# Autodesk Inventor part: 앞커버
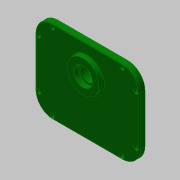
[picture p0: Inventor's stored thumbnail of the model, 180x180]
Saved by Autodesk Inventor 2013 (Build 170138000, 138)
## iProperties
Created: 2016-12
Part Number: 앞커버
Material: 일반
Document SubType Name: Modeling
Designer: mduedu
Density: 1 g/cm^3
Author: mduedu
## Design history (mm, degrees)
sketch "스케치1"
  geometry: L1 (-90, 42)-(-90, -42); L2 (-60, 72)-(60, 72); L3 (90, 42)-(90, -42); L4 (60, -72)-(-60, -72); A1 r 30 centre (-60, -42) between (-90, -42) and (-60, -72); A2 r 30 centre (60, 42) between (90, 42) and (60, 72); A3 r 30 centre (60, -42) between (60, -72) and (90, -42); A4 r 30 centre (-60, 42) between (-60, 72) and (-90, 42); 1 further point
  constraints: 8 end point, 8 point on circle, 8 tangent, 4 centre point, 3 equal radius, 2 perpendicular, 1 horizontal
  dimensions: "d89" = 30 radius of A2; "d116" = 180 distance between parallel lines of L3 L1; "d117" = 90 distance from line of point (0, 0) L1; "d118" = 72 distance from line of L2 point (0, 0); "d119" = 144 distance between parallel lines of L4 L2
extrude "돌출1" new body sketch "스케치1" distance "d3" = 10; taper "d4" = 0 deg
sketch "스케치2"
  geometry: C1 r 21 at (0, 26); 1 further point
  constraints: 1 centre point, 1 vertical alignment
  dimensions: "d5" = 42 diameter of C1; "d7" = 26 distance of C1.centre point (0, 0)
extrude "돌출2" join sketch "스케치2" distance "d8" = 7; taper "d9" = 0 deg
sketch "스케치3"
  geometry: C1 r 15 at (0, -28.87); C2 r 21 at (0, 26) reference; C3 r 15 at (-45.552, -28.87); C4 r 15 at (45.552, -28.87); 1 further point
  constraints: 3 centre point, 2 horizontal alignment, 1 vertical alignment
  dimensions: "d10" = 30 diameter of C1; "d71" = 54.87 distance of C1.centre C2.centre; "d120" = 30 diameter of C3; "d121" = 30 diameter of C4; "d122" = 45.552 distance of C3.centre C1.centre; "d123" = 45.552 distance of C4.centre C1.centre
extrude "돌출3" join sketch "스케치3" distance "d12" = 7; taper "d13" = 0 deg
sketch "스케치4"
  geometry: C1 r 21 at (0, 26) reference; C2 r 28 at (0, 26); 1 further point
  constraints: 1 centre point, 1 coincident
  dimensions: "d14" = 56 diameter of C2
extrude "돌출4" join sketch "스케치4" distance "d15" = 7; taper "d16" = -5 deg
hole "구멍1" diameter "d19" = 35; stored, may be unused: countersink angle "d23" = 90 deg, drill point angle "d25" = 0 deg; dims "d17" = 10, "d18" = 10, "d20" = 6, "d21" = 4, "d22" = 2, "d24" = 10
hole "구멍2" diameter "d28" = 22; stored, may be unused: countersink angle "d32" = 90 deg, drill point angle "d34" = 0 deg; dims "d26" = 10, "d27" = 10, "d29" = 6, "d30" = 4, "d31" = 2, "d33" = 7
hole "구멍8" diameter "d98" = 22; stored, may be unused: countersink angle "d102" = 90 deg, drill point angle "d104" = 0 deg; dims "d99" = 6, "d100" = 4, "d101" = 2, "d103" = 7, "d137" = 10, "d138" = 10
hole "구멍10" diameter "d128" = 22; stored, may be unused: countersink angle "d132" = 90 deg, drill point angle "d134" = 0 deg; dims "d129" = 6, "d130" = 4, "d131" = 2, "d133" = 7, "d135" = 10, "d136" = 10
hole "구멍3" diameter "d37" = 19; stored, may be unused: countersink angle "d41" = 90 deg, drill point angle "d43" = 0 deg; dims "d38" = 6, "d39" = 4, "d40" = 2, "d42" = 1, "d139" = 10, "d140" = 10
hole "구멍9" diameter "d107" = 19; stored, may be unused: countersink angle "d111" = 90 deg, drill point angle "d113" = 0 deg; dims "d108" = 6, "d109" = 4, "d110" = 2, "d112" = 1, "d141" = 10, "d142" = 10
hole "구멍11" diameter "d145" = 19; stored, may be unused: countersink angle "d149" = 90 deg, drill point angle "d151" = 0 deg; dims "d143" = 10, "d144" = 10, "d146" = 6, "d147" = 4, "d148" = 2, "d150" = 1
hole "구멍4" diameter "d46" = 32; stored, may be unused: countersink angle "d50" = 90 deg, drill point angle "d52" = 0 deg; dims "d47" = 6, "d48" = 4, "d49" = 2, "d51" = 8.3, "d154" = 10, "d155" = 10
hole "구멍5" diameter "d55" = 25; stored, may be unused: countersink angle "d59" = 90 deg, drill point angle "d61" = 0 deg; dims "d53" = 10, "d54" = 10, "d56" = 6, "d57" = 4, "d58" = 2, "d60" = 8
fillet "모깎기1" dims "d62" = 0.3
fillet "모깎기2" dims "d63" = 2
chamfer "모따기1" distance "d64" = 1; stored, may be unused: second distance "d65" = 2, angle "d66" = 45 deg
chamfer "모따기2" distance "d152" = 0.8; stored, may be unused: second distance "d153" = 2, angle "d156" = 30 deg
fillet "모깎기4" dims "d68" = 2
fillet "모깎기5" dims "d69" = 2
fillet "모깎기7" dims "d157" = 2
sketch "스케치5"
  geometry: L1 (60, 72)-(-60, 72) reference; L2 (90, -42)-(90, 42) reference; L3 (-60, -72)-(60, -72) reference; L4 (-90, 42)-(-90, -42) reference; L5 (-84, 42)-(-84, -42); L6 (-60, -66)-(60, -66); L7 (84, -42)-(84, 42); L8 (60, 66)-(-60, 66); A1 r 30 centre (60, 42) between (90, 42) and (60, 72) reference; A2 r 30 centre (60, -42) between (60, -72) and (90, -42) reference; A3 r 30 centre (-60, -42) between (-90, -42) and (-60, -72) reference; A4 r 30 centre (-60, 42) between (-60, 72) and (-90, 42) reference; A5 r 24 centre (-60, -42) between (-84, -42) and (-60, -66); A6 r 24 centre (60, -42) between (60, -66) and (84, -42); A7 r 24 centre (60, 42) between (84, 42) and (60, 66); A8 r 24 centre (-60, 42) between (-60, 66) and (-84, 42)
  constraints: 8 end point, 8 point on circle, 4 centre point, 7 other
  dimensions: "d93" = 6 distance between parallel lines of L5 L4
sketch "스케치7"
  geometry: L1 (60, 66)-(-60, 66) reference; L2 (84, -42)-(84, 42) reference; L3 (-60, -66)-(60, -66) reference; L4 (-84, 42)-(-84, -42) reference; A1 r 24 centre (60, 42) between (84, 42) and (60, 66) reference; A2 r 24 centre (60, -42) between (60, -66) and (84, -42) reference; A3 r 24 centre (-60, -42) between (-84, -42) and (-60, -66) reference; A4 r 24 centre (-60, 42) between (-60, 66) and (-84, 42) reference; 8 further points
  constraints: 8 coincident
hole "구멍7" sketch "스케치7" at (-84, 42), (-84, -42), (-60, -66), (60, -66), (84, -42), (84, 42), (60, 66), (-60, 66) diameter "d80" = 4.5; stored, may be unused: countersink angle "d84" = 90 deg, drill point angle "d86" = 0 deg; dims "d81" = 6, "d82" = 8, "d83" = 4.6, "d85" = 8
node "솔리드1"
